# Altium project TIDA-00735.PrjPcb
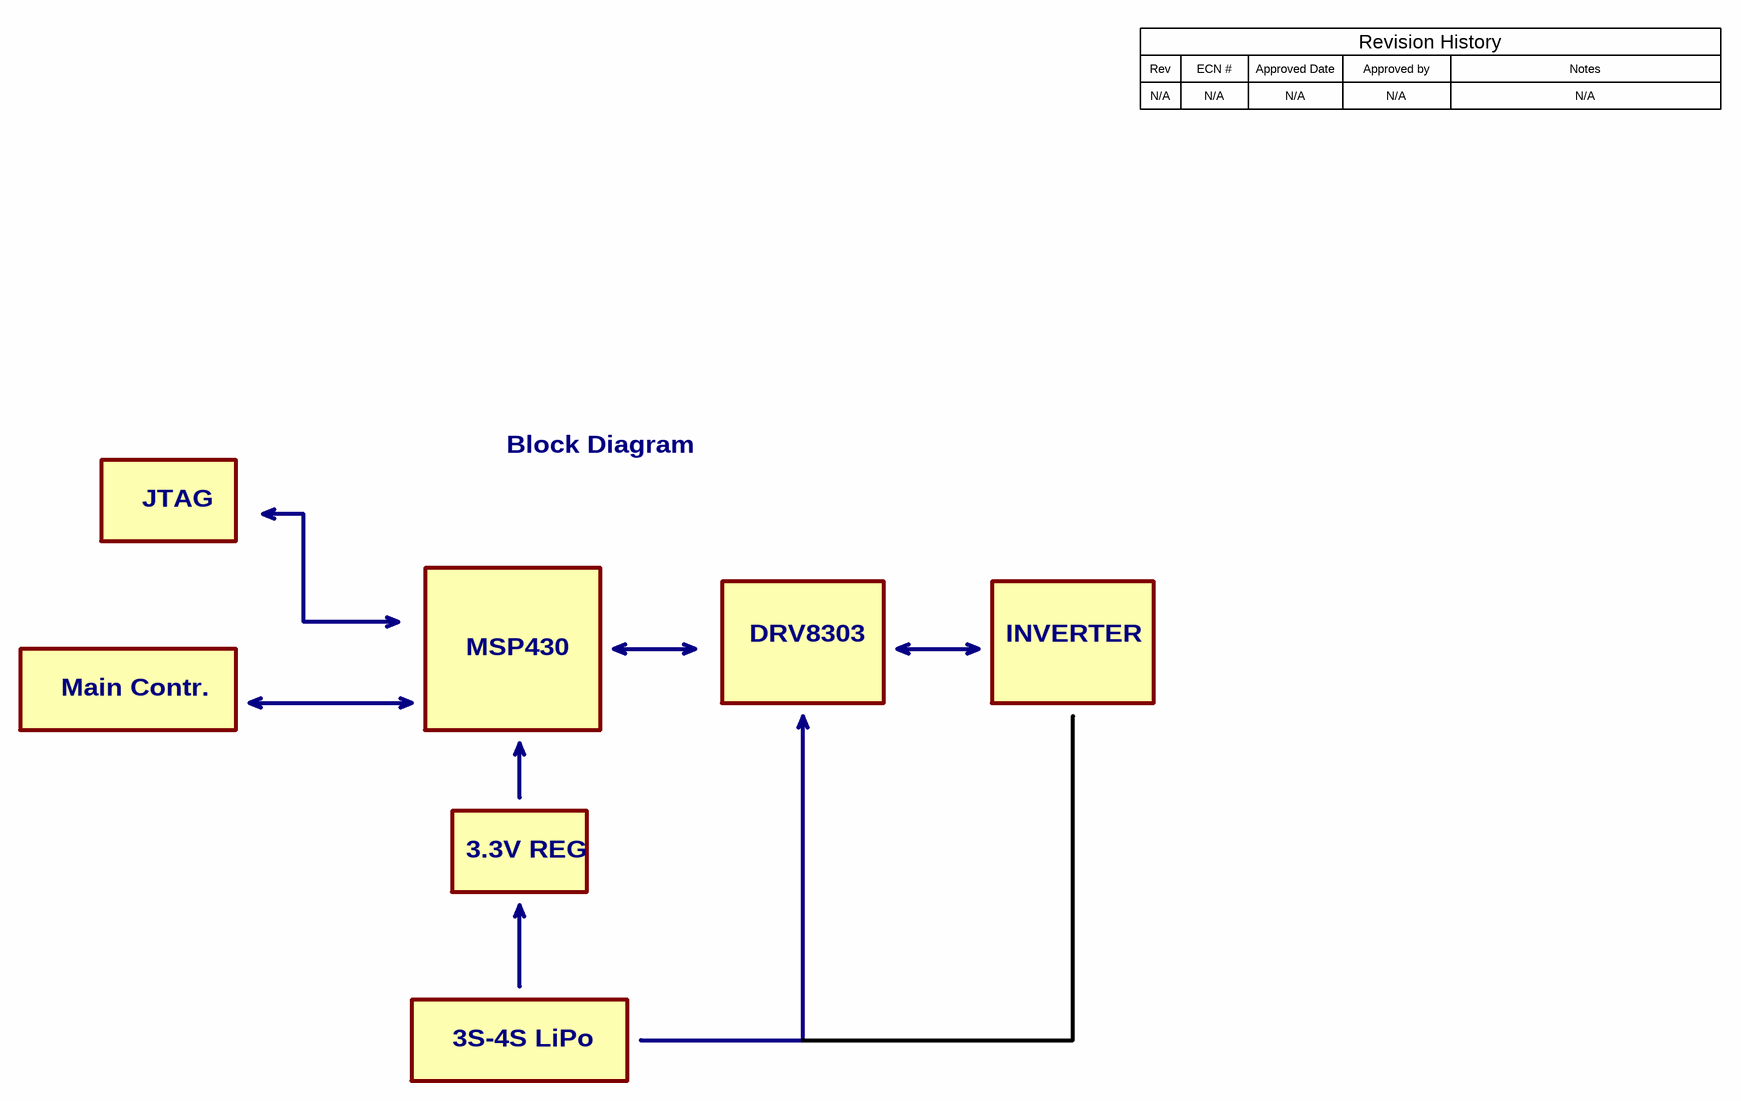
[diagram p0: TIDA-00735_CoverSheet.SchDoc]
CopyrightYear: 2015; EVM_Orderable: N/A; PCB_Layout: Axel Gao; PCB_Rev: Rev A; PRJ_Customer: Public Release; PRJ_Engineer: Axel Gao; PRJ_Number: TIDA-00735; PRJ_Title: Propeller Controller; SCH_Rev: E1; TechSupport: http://www.ti.com/support; TID: 00735
4 sheets, 70 parts. Net scope: global (net labels, ports and power ports of the same name join across sheets).
Board file: TIDA-00735_PCB.PcbDoc
Sheets:
  TIDA-00735_CoverSheet.SchDoc
  TIDA-00735_DRV8303.SchDoc
  TIDA-00735_Hardware.SchDoc
  TIDA-00735_MCU.SchDoc

## Sheet TIDA-00735_CoverSheet.SchDoc
size 431 x 279 mm; Date: Not shown in title block; ApprovedBy: Not shown in title block; CheckedBy: Not shown in title block; Author: Not shown in title block; CompanyName: Not shown in title block; Engineer: Not shown in title block; Organization: Not shown in title block; Address1: Not shown in title block; Address2: Not shown in title block; Address3: Not shown in title block; Address4: Not shown in title block; DocumentNumber: 1; Revision: Use project parameter SCH_Rev; SheetNumber: 1; SheetTotal: 3; PageSetup: Record=PageOptions¦CenterHorizontal=True¦CenterVertical=True¦PrintScale=1.00¦XCorrection=1.00¦YCorrection=1.00¦PrintKind=0¦BorderSize=5000000¦LeftOffset=0¦BottomOffset=0¦Orientation=2¦PaperLength=1000¦PaperWidth=1000¦Scale=100¦PaperSource=15¦PrintQuality=600¦MediaType=1¦DitherType=10¦PaperKind=Letter¦PrintScaleMode=1

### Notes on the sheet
- Rev
- N/A
- ECN #
- Approved Date
- Approved by
- Revision History
- Notes
- Block Diagram
- JTAG
- Main Contr.
- MSP430
- DRV8303
- INVERTER
- 3.3V REG
- 3S-4S LiPo

## Sheet TIDA-00735_DRV8303.SchDoc
size 431 x 279 mm; Date: Not shown in title block; ApprovedBy: Not shown in title block; CheckedBy: Not shown in title block; Author: Not shown in title block; CompanyName: Not shown in title block; Engineer: Not shown in title block; Organization: Not shown in title block; Address1: Not shown in title block; Address2: Not shown in title block; Address3: Not shown in title block; Address4: Not shown in title block; DocumentNumber: 1; Revision: Use project parameter SCH_Rev; SheetNumber: 2; SheetTotal: 3; PageSetup: Record=PageOptions¦CenterHorizontal=True¦CenterVertical=True¦PrintScale=1.00¦XCorrection=1.00¦YCorrection=1.00¦PrintKind=0¦BorderSize=5000000¦LeftOffset=0¦BottomOffset=0¦Orientation=2¦PaperLength=1000¦PaperWidth=1000¦Scale=100¦PaperSource=15¦PrintQuality=600¦MediaType=1¦DitherType=10¦PaperKind=Letter¦PrintScaleMode=1
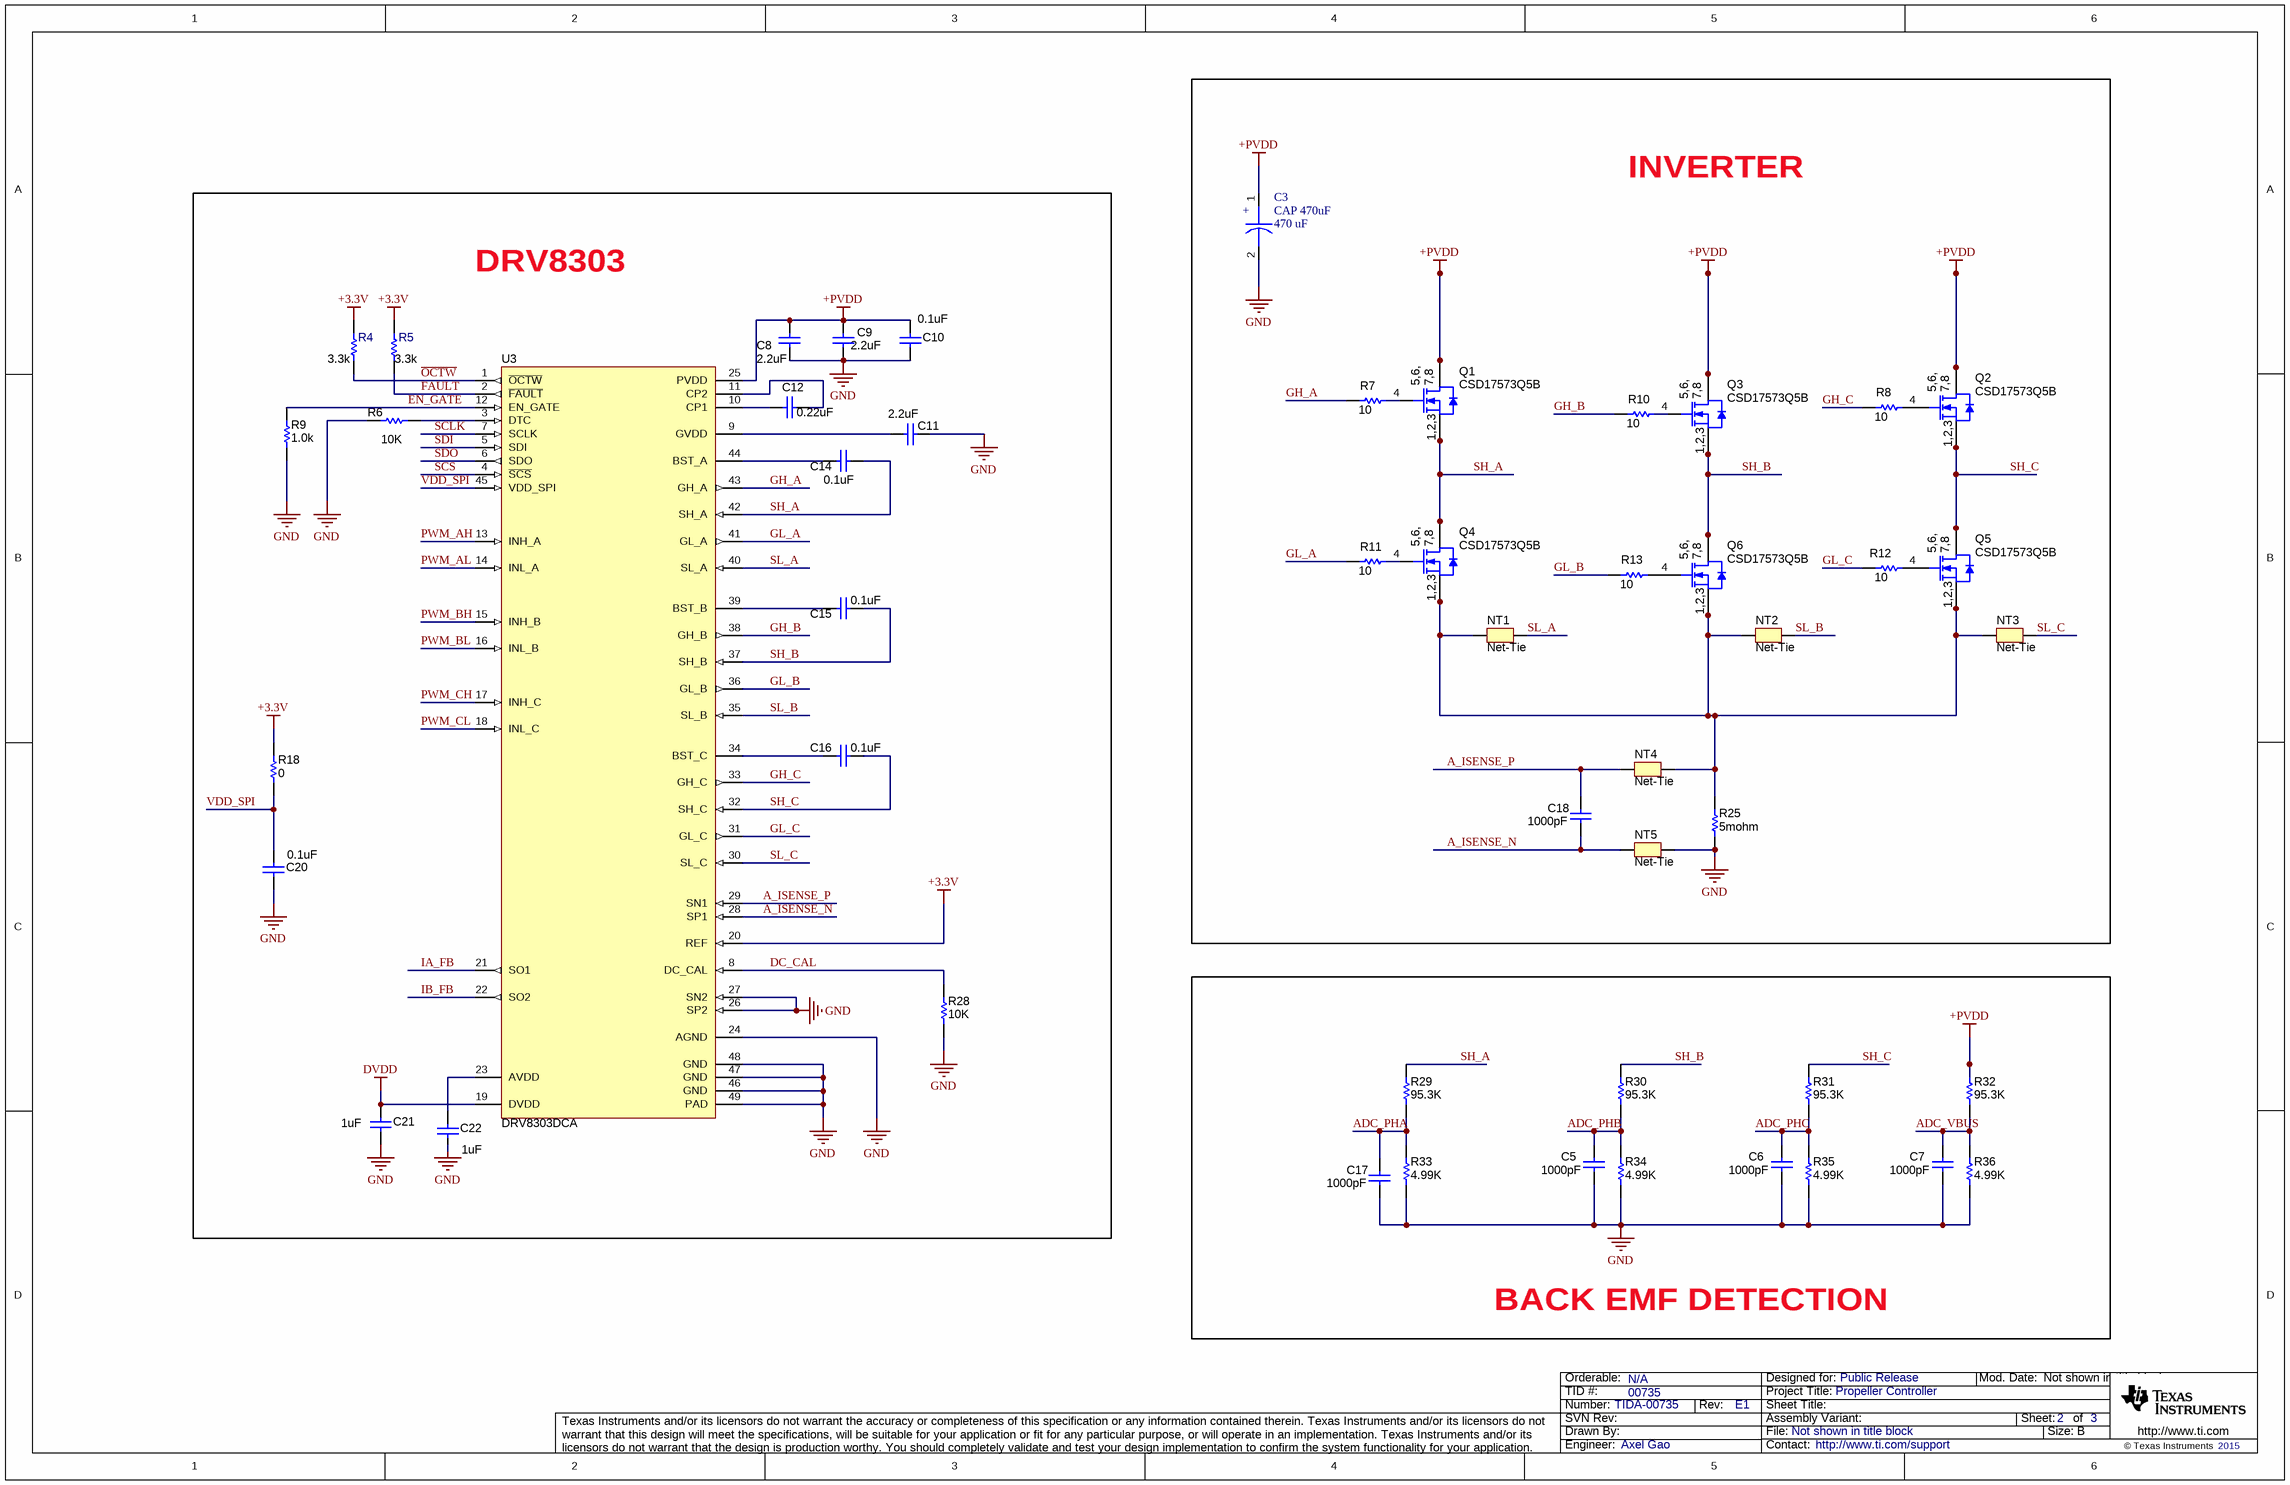
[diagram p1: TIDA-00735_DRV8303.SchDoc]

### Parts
C3  CAP 470uF  value 470 uF  [CAPAE1030X1080]
C5  ValueDisplayed: 1000pF  [0603]  (hidden comment: C0603C102J5GAC)
C6  ValueDisplayed: 1000pF  [0603]  (hidden comment: C0603C102J5GAC)
C7  ValueDisplayed: 1000pF  [0603]  (hidden comment: C0603C102J5GAC)
C8  value 2.2uF  [1210L]  (hidden comment: GRM32ER72A225KA35L)
C9  value 2.2uF  [1210L]  (hidden comment: GRM32ER72A225KA35L)
C10  value 0.1uF  [0603L]  (hidden comment: GRM188R72A104KA35D)
C11  value 2.2uF  [0805L]  (hidden comment: GRM219R61E225KA12D)
C12  value 0.22uF  [0603L]  (hidden comment: C1608X7R1H223K)
C14  value 0.1uF  [0603L]  (hidden comment: C1608X7R1H104K)
C15  value 0.1uF  [0603L]  (hidden comment: C1608X7R1H104K)
C16  value 0.1uF  [0603L]  (hidden comment: C1608X7R1H104K)
C17  ValueDisplayed: 1000pF  [0603]  (hidden comment: C0603C102J5GAC)
C18  ValueDisplayed: 1000pF  [0603]  (hidden comment: C0603C102J5GAC)
C20  value 0.1uF  [0603L]  (hidden comment: C1608X7R1E104K)
C21  value 1uF  [0603L]  (hidden comment: GRM188R61E105KA12D)
C22  value 1uF  [0603L]  (hidden comment: GRM188R61E105KA12D)
NT1  Net-Tie  [Net-Tie_10mil]  (net tie, no BOM)
NT2  Net-Tie  [Net-Tie_10milWide_30milLong]  (net tie, no BOM)
NT3  Net-Tie  [Net-Tie_10milWide_30milLong]  (net tie, no BOM)
NT4  Net-Tie  [Net-Tie_10milWide_30milLong]  (net tie, no BOM)
NT5  Net-Tie  [Net-Tie_10milWide_30milLong]  (net tie, no BOM)
Q1  CSD17573Q5B  [TRANS_NexFET_Q5B]
Q2  CSD17573Q5B  [TRANS_NexFET_Q5B]
Q3  CSD17573Q5B  [TRANS_NexFET_Q5B]
Q4  CSD17573Q5B  [TRANS_NexFET_Q5B]
Q5  CSD17573Q5B  [TRANS_NexFET_Q5B]
Q6  CSD17573Q5B  [TRANS_NexFET_Q5B]
R4  value 3.3k  [0603]  (hidden comment: CRCW06033K30JNEA)
R5  value 3.3k  [0603]  (hidden comment: CRCW06033K30JNEA)
R6  value 10K  [0603L]  (hidden comment: CRCW06031R00JNEA)
R7  value 10  [0603L]  (hidden comment: CRCW060310R0JNEA)
R8  value 10  [0603L]  (hidden comment: CRCW060310R0JNEA)
R9  value 1.0k  [0603L]  (hidden comment: CRCW06031K00JNEA)
R10  value 10  [0603L]  (hidden comment: CRCW060310R0JNEA)
R11  value 10  [0603L]  (hidden comment: CRCW060310R0JNEA)
R12  value 10  [0603L]  (hidden comment: CRCW060310R0JNEA)
R13  value 10  [0603L]  (hidden comment: CRCW060310R0JNEA)
R18  value 0  [0603L]  (hidden comment: CRCW06030000Z0EA)
R25  value 5mohm  [2512]  (hidden comment: HCJ2512ZT0R00)
R28  value 10K  [0603L]  (hidden comment: CRCW06031K00JNEA)
R29  value 95.3K  [0603L]  (hidden comment: CRCW060310R0JNEA)
R30  value 95.3K  [0603L]  (hidden comment: CRCW060310R0JNEA)
R31  value 95.3K  [0603L]  (hidden comment: CRCW060310R0JNEA)
R32  value 95.3K  [0603L]  (hidden comment: CRCW060310R0JNEA)
R33  value 4.99K  [0603L]  (hidden comment: CRCW060310R0JNEA)
R34  value 4.99K  [0603L]  (hidden comment: CRCW060310R0JNEA)
R35  value 4.99K  [0603L]  (hidden comment: CRCW060310R0JNEA)
R36  value 4.99K  [0603L]  (hidden comment: CRCW060310R0JNEA)
U3  DRV8303DCA  [DCA0048A_N]

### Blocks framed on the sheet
INVERTER: C3 C18 NT1-NT5 Q1-Q6 R7 R8 R10-R13 R25
DRV8303: C8-C12 C14-C16 C20-C22 R4-R6 R9 R18 R28 U3
BACK EMF DETECTION: C5-C7 C17 R29-R36

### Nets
+3.3V: R4.2 R5.1 R18.2 U3.20(REF)
+PVDD: C3.1 C8.1 C9.1 C10.1 Q1.5(D) Q1.6(D) Q1.7(D) Q1.8(D) Q2.5(D) Q2.6(D) Q2.7(D) Q2.8(D) Q3.5(D) Q3.6(D) Q3.7(D) Q3.8(D) R32.2 U3.25(PVDD)
DVDD: C21.1 U3.19(DVDD)
GND: C3.2 C5.2 C6.2 C7.2 C8.2 C9.2 C10.2 C11.2 C17.2 C20.2 C21.2 C22.2 NT5.2 R6.1 R9.1 R25.1 R28.1 R33.1 R34.1 R35.1 R36.1 U3.24(AGND) U3.26(SP2) U3.27(SN2) U3.46(GND) U3.47(GND) U3.48(GND) U3.49(PAD)
~{OCTW}: R4.1 U3.1(~{OCTW})
A_ISENSE_N: C18.2 NT5.1 U3.28(SP1)
A_ISENSE_P: C18.1 NT4.1 U3.29(SN1)
ADC_PHA: C17.1 R29.1 R33.2
ADC_PHB: C5.1 R30.1 R34.2
ADC_PHC: C6.1 R31.1 R35.2
ADC_VBUS: C7.1 R32.1 R36.2
DC_CAL: R28.2 U3.8(DC_CAL)
EN_GATE: R9.2 U3.12(EN_GATE)
FAULT: R5.2 U3.2(~{FAULT})
GH_A: R7.1 U3.43(GH_A)
GH_B: R10.1 U3.38(GH_B)
GH_C: R8.1 U3.33(GH_C)
GL_A: R11.1 U3.41(GL_A)
GL_B: R13.1 U3.36(GL_B)
GL_C: R12.1 U3.31(GL_C)
IA_FB: U3.21(SO1)
IB_FB: U3.22(SO2)
PWM_AH: U3.13(INH_A)
PWM_AL: U3.14(INL_A)
PWM_BH: U3.15(INH_B)
PWM_BL: U3.16(INL_B)
PWM_CH: U3.17(INH_C)
PWM_CL: U3.18(INL_C)
SCLK: U3.7(SCLK)
SCS: U3.4(~{SCS})
SDI: U3.5(SDI)
SDO: U3.6(SDO)
SH_A: C14.2 Q1.1(S) Q1.2(S) Q1.3(S) Q4.5(D) Q4.6(D) Q4.7(D) Q4.8(D) R29.2 U3.42(SH_A)
SH_B: C15.2 Q3.1(S) Q3.2(S) Q3.3(S) Q6.5(D) Q6.6(D) Q6.7(D) Q6.8(D) R30.2 U3.37(SH_B)
SH_C: C16.2 Q2.1(S) Q2.2(S) Q2.3(S) Q5.5(D) Q5.6(D) Q5.7(D) Q5.8(D) R31.2 U3.32(SH_C)
SL_A: NT1.2 U3.40(SL_A)
SL_B: NT2.2 U3.35(SL_B)
SL_C: NT3.2 U3.30(SL_C)
VDD_SPI: C20.1 R18.1 U3.45(VDD_SPI)
NetC11_1: C11.1 U3.9(GVDD)
NetC12_1: C12.1 U3.10(CP1)
NetC12_2: C12.2 U3.11(CP2)
NetC14_1: C14.1 U3.44(BST_A)
NetC15_1: C15.1 U3.39(BST_B)
NetC16_1: C16.1 U3.34(BST_C)
NetC22_1: C22.1 U3.23(AVDD)
NetNT1_1: NT1.1 NT2.1 NT3.1 NT4.2 Q4.1(S) Q4.2(S) Q4.3(S) Q5.1(S) Q5.2(S) Q5.3(S) Q6.1(S) Q6.2(S) Q6.3(S) R25.2
NetQ1_4: Q1.4(G) R7.2
NetQ2_4: Q2.4(G) R8.2
NetQ3_4: Q3.4(G) R10.2
NetQ4_4: Q4.4(G) R11.2
NetQ5_4: Q5.4(G) R12.2
NetQ6_4: Q6.4(G) R13.2
NetR6_2: R6.2 U3.3(DTC)

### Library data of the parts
C3 = CAP_33OSR100-14315EC: Capacitor, Aluminum, 50VDC, -10+20%; PartNumber: 330FWxxxV13x28; Manufacturer: Surge; Area: 283.53 mm
C5-C7 C17 C18 = C0603C102J5GAC: CAP, CERM, 1000pF, 50V, +/-5%, C0G/NP0, 0603; Manufacturer: Kemet; Polarized: N; CompType: Capacitor; U/M: EA; Cap_F: 0.000000001; Tolerance_%: 5; Value1: Unknown; VDC_V: 50; TaMin_C: -55; TaMax_C: 125
C8 C9 = GRM32ER72A225KA35L: CAP, CERM, 2.2uF, 100V, +/-10%, X7R, 1210; Manufacturer: MuRata; Polarized: N; CompType: Capacitor; U/M: EA; Cap_F: 0.0000022; Tolerance_%: 10; ESR_Ohm: 0.007; Value1: 0.007 ohm; VDC_V: 100; IRMS_A: 4.4; TaMin_C: -55; TaMax_C: 125; Cap_Case: 1210
C10 = GRM188R72A104KA35D: CAP, CERM, 0.1uF, 100V, +/-10%, X7R, 0603; Manufacturer: MuRata; Polarized: N; CompType: Capacitor; U/M: EA; Cap_F: 0.0000001; Tolerance_%: 10; Value1: Unknown; VDC_V: 100; TaMin_C: -55; TaMax_C: 125; Cap_Case: 0603
C11 = GRM219R61E225KA12D: CAP, CERM, 2.2uF, 25V, +/-10%, X5R, 0805; Manufacturer: MuRata; Polarized: N; CompType: Capacitor; U/M: EA; Cap_F: 0.0000022; Tolerance_%: 10; ESR_Ohm: 0.006; Value1: 0.006 ohm; VDC_V: 25; TaMin_C: -55; TaMax_C: 85; Cap_Case: 0805
C12 = C1608X7R1H223K: CAP, CERM, 0.022uF, 50V, +/-10%, X7R, 0603; Manufacturer: TDK; Polarized: N; CompType: Capacitor; U/M: EA; Cap_F: 0.000000022; Tolerance_%: 10; ESR_Ohm: 0.0383; Value1: 0.0383 ohm; VDC_V: 50; TaMin_C: -55; TaMax_C: 125; Cap_Case: 0603
C14-C16 = C1608X7R1H104K: CAP, CERM, 0.1uF, 50V, +/-10%, X7R, 0603; Manufacturer: TDK; Polarized: N; CompType: Capacitor; U/M: EA; Cap_F: 0.0000001; Tolerance_%: 10; ESR_Ohm: 0.017; Value1: 0.017 ohm; VDC_V: 50; TaMin_C: -55; TaMax_C: 125; Cap_Case: 0603
C20 = C1608X7R1E104K: CAP, CERM, 0.1uF, 25V, +/-10%, X7R, 0603; Manufacturer: TDK; Polarized: N; CompType: Capacitor; ValueDisplayed: 0.1礔, DNP; U/M: EA; Cap_F: 0.0000001; Tolerance_%: 10; ESR_Ohm: 0.017; Value1: 0.017 ohm; VDC_V: 25; TaMin_C: -55; TaMax_C: 125; Cap_Case: 0603
C21 C22 = GRM188R61E105KA12D: CAP, CERM, 1uF, 25V, +/-10%, X5R, 0603; Manufacturer: MuRata; Polarized: N; CompType: Capacitor; U/M: EA; Cap_F: 0.000001; Tolerance_%: 10; Value1: Unknown; VDC_V: 25; TaMin_C: -55; TaMax_C: 85; Cap_Case: 0603
NT1-NT5 = Net-Tie: Single point connection between nets.; SymbolCreator: codlsc
Q1-Q6 = CSD17573Q5B: MOSFET, N-CH, 30 V, 100 A, SON 5x6mm; Manufacturer: Texas Instruments; Alternate Manufacturer: None; U/M: EA; ChType: N; Value: 30V; VdsMax_V: 30; Value1: 0.00145 ohm; Rdson45_ohm: 0.00145; Value2: 49 nC; QgTyp_nC: 49; Vgs_V: 20; IdsMax_A: 100; AEC Category: Q101
R4 R5 = CRCW06033K30JNEA: RES, 3.3 k, 5%, 0.1 W, 0603; Manufacturer: Vishay-Dale; CompType: Resistor; Res_ohm: 3300; Value_Code: 3k30; Tolerance_%: 5; Power_W: 0.1; Value2: 0.1W; VDC_V: 75; TempCo: 200 ppm/C; EIA_Code: E24; U/M: EA
R6 = CRCW06031R00JNEA: RES, 1.0 ohm, 5%, 0.1W, 0603; Manufacturer: Vishay-Dale; CompType: Resistor; Res_ohm: 1; Value_Code: 1R00; Tolerance_%: 5; Power_W: 0.1; VDC_V: 75; TempCo: 200 ppm/C; EIA_Code: E24; U/M: EA
R7 R8 R10-R13 = CRCW060310R0JNEA: RES, 10 ohm, 5%, 0.1W, 0603; Manufacturer: Vishay-Dale; CompType: Resistor; Value_Code: 10R0; Tolerance_%: 5; Power_W: 0.1; VDC_V: 75; TempCo: 200 ppm/C; EIA_Code: E24; U/M: EA
R9 R28 = CRCW06031K00JNEA: RES, 1.0k ohm, 5%, 0.1W, 0603; Manufacturer: Vishay-Dale; CompType: Resistor; Res_ohm: 1000; Value_Code: 1k00; Tolerance_%: 5; Power_W: 0.1; VDC_V: 75; TempCo: 200 ppm/C; EIA_Code: E24; U/M: EA
R18 = CRCW06030000Z0EA: RES, 0 ohm, 5%, 0.1W, 0603; Manufacturer: Vishay-Dale; CompType: Resistor; Value_Code: 0000; Tolerance_%: 5; Power_W: 0.1; VDC_V: 75; TempCo: 200 ppm/C; EIA_Code: E24; U/M: EA
R25 = ERJ-M1WSF5M0U: RES, 5 mohm, 63.2A JUMP, 2512; Manufacturer: Panasonic; CompType: Resistor; Res_ohm: 0; Value_Code: R005; Tolerance_%: 1; Value1: 1%; Value2: 1W; TempCo: 100 ppm/C; EIA_Code: E96; U/M: EA
R29-R36 = CRCW060310R0JNEA: RES, 10 ohm, 5%, 0.1W, 0603; Manufacturer: Vishay-Dale; CompType: Resistor; Res_ohm: 10; Value_Code: 10R0; Tolerance_%: 5; Power_W: 0.1; VDC_V: 75; TempCo: 200 ppm/C; EIA_Code: E24; U/M: EA
U3 = DRV8303DCA: THREE PHASE PRE-DRIVER WITH DUAL CURRENT SHUNT AMPLIFIERS, DCA0048A; Manufacturer: Texas Instruments; SymbolCreator: x0208325; CompType: IC; U/M: EA

## Sheet TIDA-00735_Hardware.SchDoc
size 431 x 279 mm; Date: Not shown in title block; ApprovedBy: Not shown in title block; CheckedBy: Not shown in title block; Author: Not shown in title block; CompanyName: Not shown in title block; Engineer: Not shown in title block; Organization: Not shown in title block; Address1: Not shown in title block; Address2: Not shown in title block; Address3: Not shown in title block; Address4: Not shown in title block; DocumentNumber: 1; Revision: Use project parameter SCH_Rev; SheetNumber: 3; SheetTotal: 3; PageSetup: Record=PageOptions¦CenterHorizontal=True¦CenterVertical=True¦PrintScale=1.00¦XCorrection=1.00¦YCorrection=1.00¦PrintKind=0¦BorderSize=5000000¦LeftOffset=0¦BottomOffset=0¦Orientation=2¦PaperLength=1000¦PaperWidth=1000¦Scale=100¦PaperSource=15¦PrintQuality=600¦MediaType=1¦DitherType=10¦PaperKind=Letter¦PrintScaleMode=1
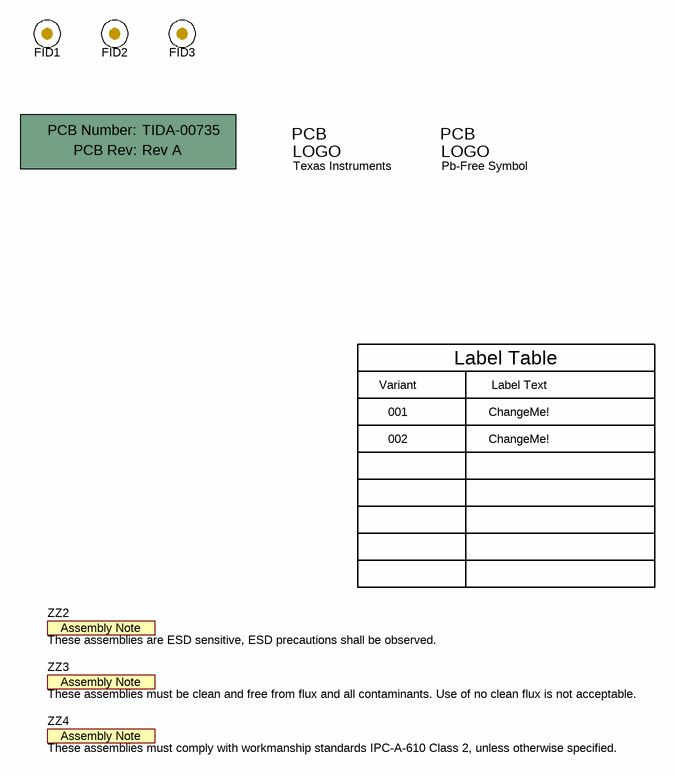
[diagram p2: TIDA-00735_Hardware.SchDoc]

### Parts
!PCB  Printed Circuit Board  (value not drawn)  (mechanical)
FID1  Fiducial  [Fiducial10-20]  (value not drawn)
FID2  Fiducial  [Fiducial10-20]  (value not drawn)
FID3  Fiducial  [Fiducial10-20]  (value not drawn)
Logo1  Texas Instruments  [TI_Stacked_Overlay_Small]  (no BOM)
Logo2  Pb-Free Symbol  [Pb-Free_Overlay_Small]  (no BOM)
ZZ2  These assemblies are ESD sensitive, ESD precautions shall be observed.  [AssemblyNote]  (no BOM)
ZZ3  These assemblies must be clean and free from flux and all contaminants. Use of no clean flux is not acceptable.  [AssemblyNote]  (no BOM)
ZZ4  These assemblies must comply with workmanship standards IPC-A-610 Class 2, unless otherwise specified.  [AssemblyNote]  (no BOM)

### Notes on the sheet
- Variant
- Label Table
- Label Text
- 001
- 002
- ChangeMe!

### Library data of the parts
!PCB = PCB: Manufacturer: Any; PartNumber: TIDA-00735; SymbolCreator: a0412235
FID1-FID3 = Fiducial: Fiducial mark.  There is nothing to buy or mount.; SymbolCreator: codlsc
Logo1 = TI_Logo: Texas Instrument Corporate Signature; SymbolCreator: codlsc
Logo2 = Pb-Free: SymbolCreator: a0412235
ZZ2-ZZ4 = AssemblyNote: SymbolCreator: codlsc

## Sheet TIDA-00735_MCU.SchDoc
size 431 x 279 mm; Date: Not shown in title block; ApprovedBy: Not shown in title block; CheckedBy: Not shown in title block; Author: Not shown in title block; CompanyName: Not shown in title block; Engineer: Not shown in title block; Organization: Not shown in title block; Address1: Not shown in title block; Address2: Not shown in title block; Address3: Not shown in title block; Address4: Not shown in title block; DocumentNumber: 1; Revision: Use project parameter SCH_Rev; SheetNumber: 2; SheetTotal: 3; PageSetup: Record=PageOptions¦CenterHorizontal=True¦CenterVertical=True¦PrintScale=1.00¦XCorrection=1.00¦YCorrection=1.00¦PrintKind=0¦BorderSize=5000000¦LeftOffset=0¦BottomOffset=0¦Orientation=2¦PaperLength=1000¦PaperWidth=1000¦Scale=100¦PaperSource=15¦PrintQuality=600¦MediaType=1¦DitherType=10¦PaperKind=Letter¦PrintScaleMode=1
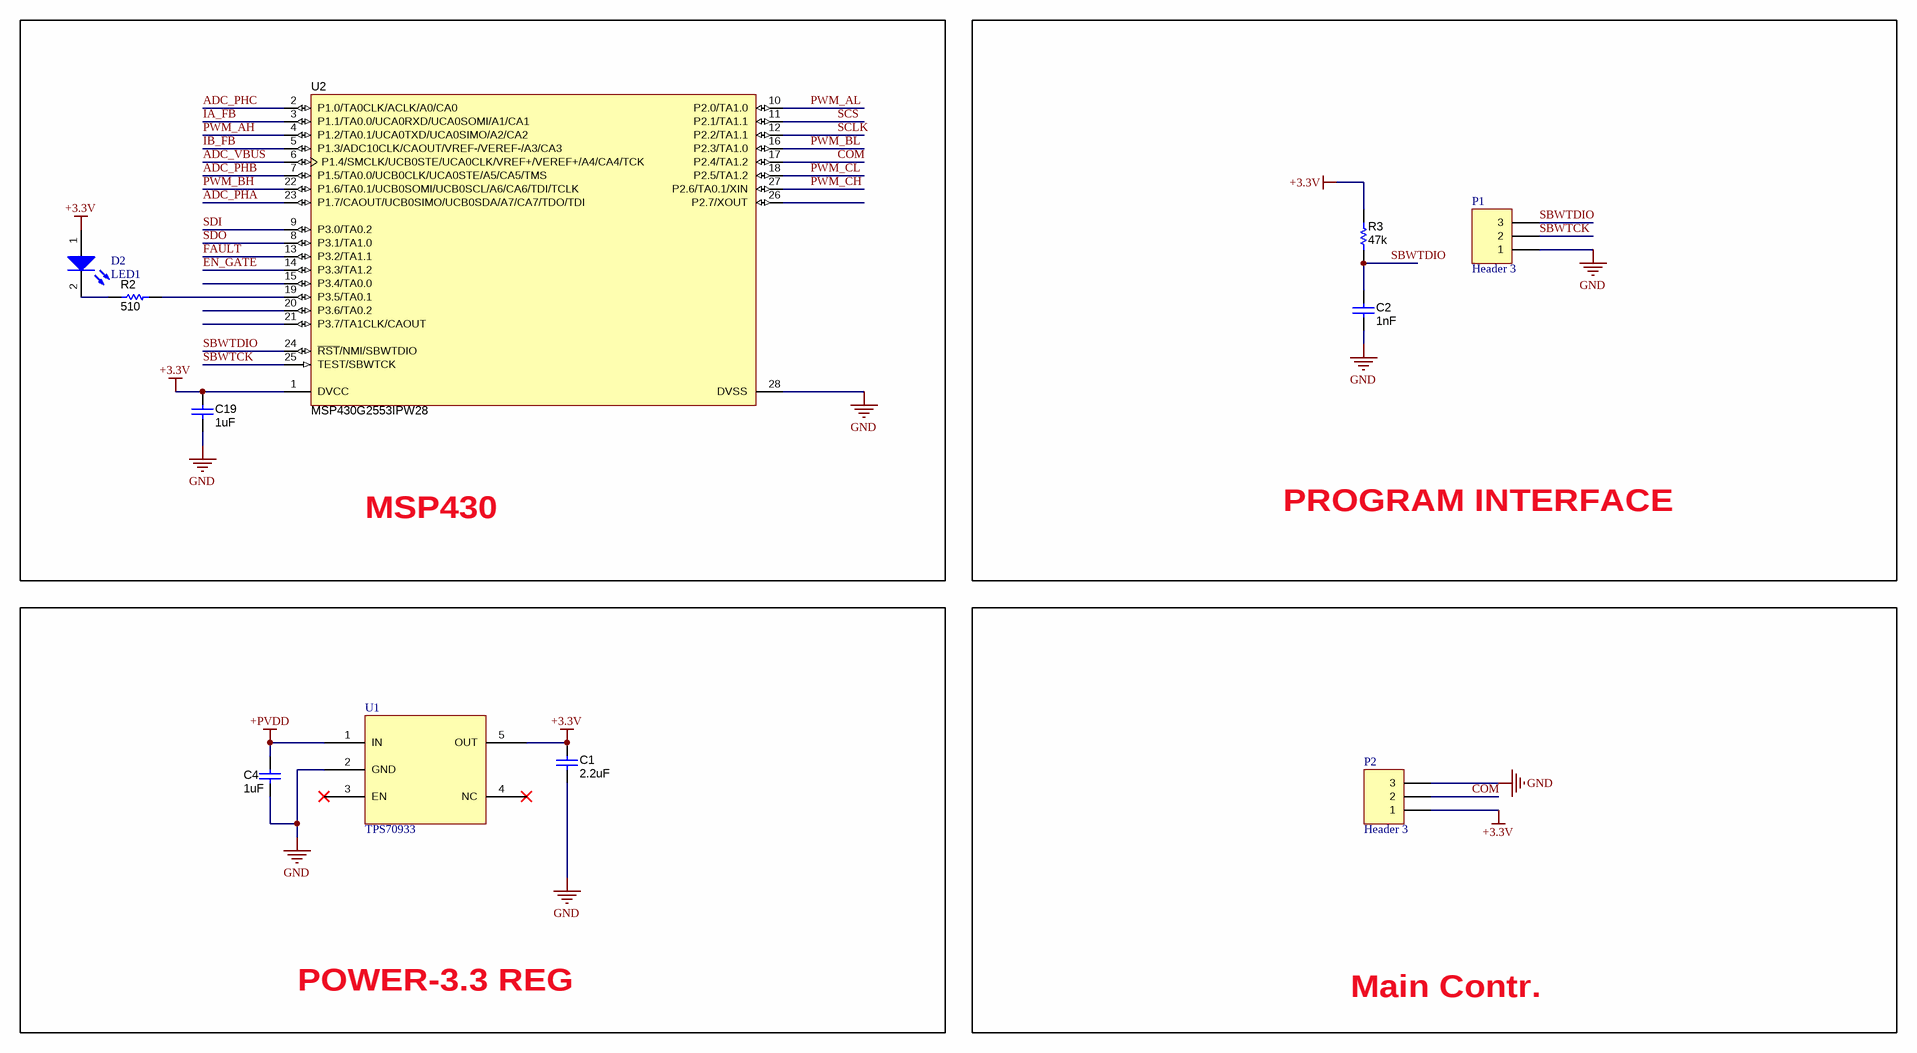
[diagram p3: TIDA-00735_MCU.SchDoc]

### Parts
C1  ValueDisplayed: 2.2uF  [6-0805_M]  (hidden comment: CAP)
C2  ValueDisplayed: 1nF  [0603]  (hidden comment: CAP)
C4  ValueDisplayed: 1uF  [6-0805_N]  (hidden comment: CAP)
C19  value 1uF  [0805L]  (hidden comment: GRM219R61E225KA12D)
D2  LED1  [6-0805_L]
P1  Header 3  [HDR1X3]
P2  Header 3  [HDR1X3]
R2  ValueDisplayed: 510  [0603]  (hidden comment: RES)
R3  ValueDisplayed: 47k  [0603]  (hidden comment: RES)
U1  TPS70933  [DBV0005A_N]
U2  MSP430G2553IPW28  [PW0028A_N]

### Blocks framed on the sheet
MSP430: C19 D2 R2 U2
PROGRAM INTERFACE: C2 P1 R3
POWER-3.3 REG: C1 C4 U1
Main Contr.: P2

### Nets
+3.3V: C1.1 C19.2 D2.1(A) P2.1 R3.2 U1.5(OUT) U2.1(DVCC)
+PVDD: C4.1 U1.1(IN)
GND: C1.2 C2.2 C4.2 C19.1 P1.1 P2.3 U1.2(GND) U2.28(DVSS)
ADC_PHA: U2.23(P1.7/CAOUT/UCB0SIMO/UCB0SDA/A7/CA7/TDO/TDI)
ADC_PHB: U2.7(P1.5/TA0.0/UCB0CLK/UCA0STE/A5/CA5/TMS)
ADC_PHC: U2.2(P1.0/TA0CLK/ACLK/A0/CA0)
ADC_VBUS: U2.6(P1.4/SMCLK/UCB0STE/UCA0CLK/VREF+/VEREF+/A4/CA4/TCK)
COM: P2.2 U2.17(P2.4/TA1.2)
EN_GATE: U2.14(P3.3/TA1.2)
FAULT: U2.13(P3.2/TA1.1)
IA_FB: U2.3(P1.1/TA0.0/UCA0RXD/UCA0SOMI/A1/CA1)
IB_FB: U2.5(P1.3/ADC10CLK/CAOUT/VREF-/VEREF-/A3/CA3)
PWM_AH: U2.4(P1.2/TA0.1/UCA0TXD/UCA0SIMO/A2/CA2)
PWM_AL: U2.10(P2.0/TA1.0)
PWM_BH: U2.22(P1.6/TA0.1/UCB0SOMI/UCB0SCL/A6/CA6/TDI/TCLK)
PWM_BL: U2.16(P2.3/TA1.0)
PWM_CH: U2.27(P2.6/TA0.1/XIN)
PWM_CL: U2.18(P2.5/TA1.2)
SBWTCK: P1.2 U2.25(TEST/SBWTCK)
SBWTDIO: C2.1 P1.3 R3.1 U2.24(~{RST}/NMI/SBWTDIO)
SCLK: U2.12(P2.2/TA1.1)
SCS: U2.11(P2.1/TA1.1)
SDI: U2.9(P3.0/TA0.2)
SDO: U2.8(P3.1/TA1.0)
NetD2_2: D2.2(K) R2.1
NetR2_2: R2.2 U2.19(P3.5/TA0.1)

Not connected (* = marked no-connect by the designer): U1 3(EN)* 4(NC)*; U2 15(P3.4/TA0.0) 20(P3.6/TA0.2) 21(P3.7/TA1CLK/CAOUT) 26(P2.7/XOUT)

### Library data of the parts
C1 C4 = C0603C105K8PACTU: Manufacturer: Kemet; Polarized: N; CompType: Capacitor; Value: 1uF; U/M: EA; Cap_F: 0.000001; Tolerance_%: 10; Value1: Unknown; Value2: 10V; TempCo: X5R; TaMin_C: -55; TaMax_C: 85; Cap_Case: 0603
C2 = C0603C105K8PACTU: Manufacturer: Kemet; Polarized: N; CompType: Capacitor; Value: 1uF; U/M: EA; Cap_F: 0.000001; Tolerance_%: 10; Value1: Unknown; Value2: 10V; TempCo: X5R; TaMin_C: -55; TaMax_C: 85
C19 = GRM219R61E225KA12D: CAP, CERM, 1uF, 25V, +/-10%, X5R, 0805; Manufacturer: MuRata; Polarized: N; CompType: Capacitor; ValueDisplayed: 2.2礔; U/M: EA; Cap_F: 0.0000022; Tolerance_%: 10; ESR_Ohm: 0.006; Value1: 0.006 ohm; VDC_V: 25; TaMin_C: -55; TaMax_C: 85; Cap_Case: 0805
D2 = LED2: Typical RED, GREEN, YELLOW, AMBER GaAs LED
P1 P2 = Header 3: Header, 3-Pin
R2 R3 = CRCW060330K0JNEA: Manufacturer: Vishay-Dale; CompType: Resistor; Value: 30k; Res_ohm: 30000; Value_Code: 30k0; Tolerance_%: 5; Value1: 5%; Power_W: 0.1; Value2: 0.1W; VDC_V: 75; TempCo: 200 ppm/C; EIA_Code: E24; U/M: EA
U1 = TPS709
U2 = MSP430G2553IPW28: Mixed Signal Microcontroller, PW0028A; Manufacturer: Texas Instruments; ADC: 10-bit SAR; ADC Channels: 8; Brown Out Reset: Yes; Eco-Plan: Green (RoHS & no Sb/Br); Flash(KB): 16; GPIO: 24; SRAM(B): 512; SubFamily: Value Line; Timers - 16-bit: 2; USCI_A (UART/LIN/IrDA/SPI): 1; SymbolCreator: Altium/a0412235; CompType: IC; U/M: EA

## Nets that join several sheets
+3.3V: TIDA-00735_DRV8303 (R4.2 R5.1 R18.2 U3.20), TIDA-00735_MCU (7 pins)
+PVDD: TIDA-00735_DRV8303 (18 pins), TIDA-00735_MCU (C4.1 U1.1)
GND: TIDA-00735_DRV8303 (28 pins), TIDA-00735_MCU (8 pins)
ADC_PHA: TIDA-00735_DRV8303 (C17.1 R29.1 R33.2), TIDA-00735_MCU (U2.23)
ADC_PHB: TIDA-00735_DRV8303 (C5.1 R30.1 R34.2), TIDA-00735_MCU (U2.7)
ADC_PHC: TIDA-00735_DRV8303 (C6.1 R31.1 R35.2), TIDA-00735_MCU (U2.2)
ADC_VBUS: TIDA-00735_DRV8303 (C7.1 R32.1 R36.2), TIDA-00735_MCU (U2.6)
EN_GATE: TIDA-00735_DRV8303 (R9.2 U3.12), TIDA-00735_MCU (U2.14)
FAULT: TIDA-00735_DRV8303 (R5.2 U3.2), TIDA-00735_MCU (U2.13)
IA_FB: TIDA-00735_DRV8303 (U3.21), TIDA-00735_MCU (U2.3)
IB_FB: TIDA-00735_DRV8303 (U3.22), TIDA-00735_MCU (U2.5)
PWM_AH: TIDA-00735_DRV8303 (U3.13), TIDA-00735_MCU (U2.4)
PWM_AL: TIDA-00735_DRV8303 (U3.14), TIDA-00735_MCU (U2.10)
PWM_BH: TIDA-00735_DRV8303 (U3.15), TIDA-00735_MCU (U2.22)
PWM_BL: TIDA-00735_DRV8303 (U3.16), TIDA-00735_MCU (U2.16)
PWM_CH: TIDA-00735_DRV8303 (U3.17), TIDA-00735_MCU (U2.27)
PWM_CL: TIDA-00735_DRV8303 (U3.18), TIDA-00735_MCU (U2.18)
SCLK: TIDA-00735_DRV8303 (U3.7), TIDA-00735_MCU (U2.12)
SCS: TIDA-00735_DRV8303 (U3.4), TIDA-00735_MCU (U2.11)
SDI: TIDA-00735_DRV8303 (U3.5), TIDA-00735_MCU (U2.9)
SDO: TIDA-00735_DRV8303 (U3.6), TIDA-00735_MCU (U2.8)

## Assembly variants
001: not fitted FID1 FID2 FID3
